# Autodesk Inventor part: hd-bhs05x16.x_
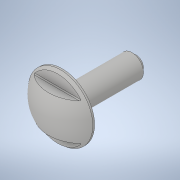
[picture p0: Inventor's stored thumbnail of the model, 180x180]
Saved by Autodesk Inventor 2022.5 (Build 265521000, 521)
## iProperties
Created: 2021-02
Part Number: hd-bhs05x16.x_
Material: 一般
Document SubType Name: Modeling
Designer: ImaoCorp
Density: 1 g/cm^3
Appearance: 既定
Sending System: SOLIDWORKS 2019-2019304
MC: AMD64
MC_MODEL: Intel64 Family 6 Model 60 Stepping 3, GenuineIntel
OS: Windows_NT
FRU: Parasolid Version 31.0, build 290,  9- 1-2019
FORMAT: text
GUISE: transmit
KEY: hd-bhs05x16
FILE: hd-bhs05x16.x_t
DATE: Mon Feb 22 15:01:37 2021
Author: ImaoCorp
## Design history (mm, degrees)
feature "Base1"
node "ソリッド1"
